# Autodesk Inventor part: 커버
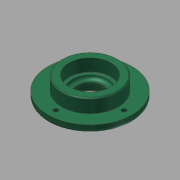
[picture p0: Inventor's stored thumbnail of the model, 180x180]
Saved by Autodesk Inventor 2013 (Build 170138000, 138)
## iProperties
Company: 한국ATC센터
Created: 2014-10
Part Number: 커버
Document SubType Name: Modeling
Designer: KYOUNG IL JANG
Density: 7.86 g/cm^3
Mass: 351.567 g
Surface Area: 161.165 cm^2
Volume: 44.7286 cm^3
Material: 강철, 연강
d0: 80.000 mm
d1: 7.000 mm
d2: 0.00 deg
d3: 54.000 mm
d4: 13.000 mm
d5: 0.00 deg
d6: 40.000 mm
d7: 5.000 mm
d8: 0.00 deg
d11: 25.000 mm
d13: 32.000 mm
d14: 8.300 mm
d20: 34.000 mm
d22: 40.000 mm
d23: 12.000 mm
d25: 3.000 mm
d27: 0.300 mm
d28: 1.000 mm
d31: 1.200 mm
d33: 30.00 deg
d34: 3.000 mm
d35: 65.000 mm
d36: 4.500 mm
d38: 8.000 mm
d39: 4.400 mm
d43: 4.000 ul
d44: 360.00 deg
Author: KYOUNG IL JANG
Revision Number: 1
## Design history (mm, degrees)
sketch "스케치1"
  geometry: C1 r 40 at (0, 0); 1 further point
  constraints: 1 centre point, 1 coincident
  dimensions: "d0" = 80 diameter of C1
extrude "돌출1" new body sketch "스케치1" distance "d1" = 7; taper "d2" = 0 deg
sketch "스케치2"
  geometry: C1 r 27 at (0, 0); 1 further point
  constraints: 1 centre point, 1 coincident
  dimensions: "d3" = 54 diameter of C1
extrude "돌출2" join sketch "스케치2" distance "d4" = 13; taper "d5" = 0 deg
sketch "스케치3"
  geometry: C1 r 20 at (0, 0); 1 further point
  constraints: 1 centre point, 1 coincident
  dimensions: "d6" = 40 diameter of C1
extrude "돌출3" join sketch "스케치3" distance "d7" = 5; taper "d8" = 0 deg
hole "구멍1" diameter "d11" = 25; stored, may be unused: countersink angle "d15" = 90 deg, drill point angle "d17" = 118 deg; dims "d9" = 10, "d10" = 10, "d12" = 6, "d13" = 32, "d14" = 8.3, "d16" = 8
hole "구멍2" diameter "d20" = 34; stored, may be unused: countersink angle "d24" = 90 deg, drill point angle "d26" = 0 deg; dims "d18" = 10, "d19" = 10, "d21" = 6, "d22" = 40, "d23" = 12, "d25" = 3
fillet "모깎기2" dims "d34" = 3
fillet "모깎기1" dims "d27" = 0.3
chamfer "모따기1" distance "d28" = 1; stored, may be unused: second distance "d29" = 2, angle "d30" = 45 deg
chamfer "모따기2" distance "d31" = 1.2; stored, may be unused: second distance "d32" = 2, angle "d33" = 30 deg
sketch "스케치4" dims "d35" = 65
  geometry: 3 further points
  constraints: 2 horizontal alignment, 1 coincident, 2 other
hole "구멍3" sketch "스케치4" at (32.5, 0) diameter "d36" = 4.5; stored, may be unused: countersink angle "d40" = 90 deg, drill point angle "d42" = 118 deg; dims "d37" = 6, "d38" = 8, "d39" = 4.4, "d41" = 13
node "솔리드1"
pattern_circular "원형 패턴1" dims count "d43" = 4, angle "d44" = 360 deg
